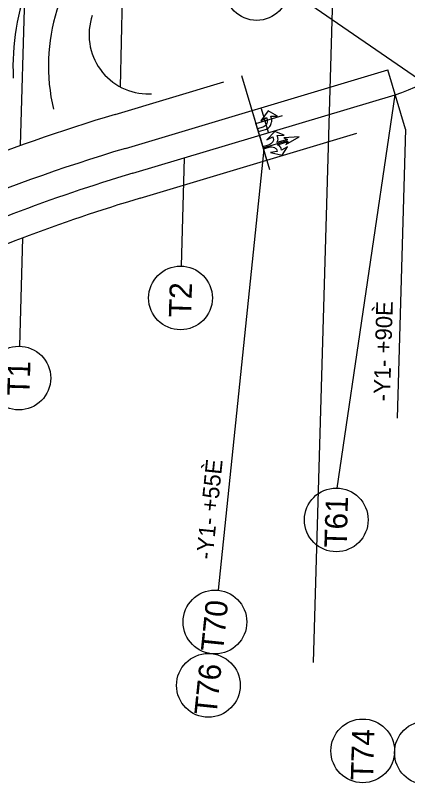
# Model space of a CAD drawing. Extents: x 1657109 to 2100937, y 684916 to 883211.
# Drawn here: x 2097527.1 to 2097693.3, y 685572.2 to 685898 of the extents above; entities that cross this region are included whole.
import ezdxf

# ---------------------------------------------------------------- set-up
doc = ezdxf.new("R2010")
doc.units = 0
for name, color, linetype in [('Default', 7, 'Continuous'), ('Prop CMT Pvmt Course 1', 7, 'Continuous'), ('Prop CMT Pvmt Gravel', 7, 'Continuous'), ('Prop Conc 1ft 6in Curb and Gutter', 7, 'Continuous'), ('Prop Conc 2ft 6in Curb and Gutter', 7, 'Continuous'), ('Prop Dimension', 7, 'Continuous'), ('Prop Guardrail Anchor Unit CELL', 7, 'Continuous'), ('Prop Lane Arrow CELL', 7, 'Continuous'), ('Prop Lane Lines', 7, 'Continuous'), ('Prop Paved Shoulder', 7, 'Continuous'), ('Prop Sign E Chevron Right', 7, 'Continuous'), ('Scratch_Level_1', 7, 'Continuous')]:
    doc.layers.add(name, color=color, linetype=linetype)

# ---------------------------------------------------------------- blocks, each defined once
blk = doc.blocks.new('SLRARR')
at = {"layer": 'Default'}
for points in [[(4.895, -0.375), (8.667, -0.375), (7.667, -1.187), (12.75, 0), (7.667, 1.187), (8.667, 0.375), (4.895, 0.375), (5.26, 0.719), (5.468, 0.983), (5.628, 1.319), (5.708, 1.595), (5.772, 1.944), (5.75, 2.563), (8, 2.063), (5.417, 4.187), (1.917, 2.188), (4.167, 2.563), (4.155, 2.076), (4.138, 1.788), (4.042, 1.499), (3.866, 1.247), (3.674, 0.995), (3.322, 0.743), (2.889, 0.551), (2.425, 0.431), (1.896, 0.37), (0, 0.375), (0, -0.375), (1.94, -0.375)], [(4.895, -0.375), (8.667, -0.375), (7.667, -1.187), (12.75, 0), (7.667, 1.187), (8.667, 0.375), (4.895, 0.375), (5.26, 0.719), (5.468, 0.983), (5.628, 1.319), (5.708, 1.595), (5.772, 1.944), (5.75, 2.563), (8, 2.063), (5.417, 4.187), (1.917, 2.188), (4.167, 2.563), (4.155, 2.076), (4.138, 1.788), (4.042, 1.499), (3.866, 1.247), (3.674, 0.995), (3.322, 0.743), (2.889, 0.551), (2.425, 0.431), (1.896, 0.37), (0, 0.375), (0, -0.375), (1.94, -0.375)], [(1.94, -0.375), (2.425, -0.43), (2.889, -0.55), (3.322, -0.742), (3.674, -0.994), (3.866, -1.247), (4.042, -1.499), (4.138, -1.788), (4.155, -2.076), (4.167, -2.563), (1.917, -2.188), (5.417, -4.187), (8, -2.062), (5.75, -2.563), (5.772, -1.944), (5.708, -1.595), (5.628, -1.319), (5.468, -0.982), (5.26, -0.718), (4.895, -0.375)], [(1.94, -0.375), (2.425, -0.43), (2.889, -0.55), (3.322, -0.742), (3.674, -0.994), (3.866, -1.247), (4.042, -1.499), (4.138, -1.788), (4.155, -2.076), (4.167, -2.563), (1.917, -2.188), (5.417, -4.187), (8, -2.062), (5.75, -2.563), (5.772, -1.944), (5.708, -1.595), (5.628, -1.319), (5.468, -0.982), (5.26, -0.718), (4.895, -0.375)]]:
    blk.add_lwpolyline(points, dxfattribs=at)

msp = doc.modelspace()

# ---------------------------------------------------------------- linework, layer by layer
at = {"layer": 'Prop CMT Pvmt Gravel'}
for p, q in [((2097571.62, 685867.71), (2097574.3, 685983.02)), ((2097529.26, 685842.85), (2097532.63, 685958.71)), ((2097642.82, 685909.02), (2097700.19, 685869.55)), ((2097663.44, 685697.81), (2097688.01, 685864.41)), ((2097692.39, 685849.78), (2097688.83, 685727.48)), ((2097632.3, 685841.3), (2097613.03, 685654.52)), ((2097597.45, 685791.82), (2097598.78, 685837.71)), ((2097528.95, 685757.9), (2097530.28, 685803.79))]:
    msp.add_line(p, q, dxfattribs=at)
for centre in [(2097629.33, 685909.41), (2097597.05, 685778.33), (2097528.55, 685744.4), (2097663.05, 685684.32), (2097611.64, 685641.09), (2097608.87, 685614.24), (2097674.26, 685586.49), (2097701.25, 685585.71)]:
    msp.add_circle(centre, 13.5, dxfattribs=at)
at = {"layer": 'Prop Conc 1ft 6in Curb and Gutter'}
msp.add_line((2097576.85, 685831.15), (2097688.01, 685864.41), dxfattribs=at)
msp.add_arc((2097791.55, 685113.58), 749, 106.65716, 114.87261, dxfattribs=at)
at = {"layer": 'Prop Conc 2ft 6in Curb and Gutter'}
msp.add_arc((2097665.53, 685934.68), 73.78, 287.7359, 0.5072, dxfattribs=at)
at = {"layer": 'Prop Dimension'}
for p, q in [((2097634.9, 685832.59), (2097623, 685872.38)), ((2097634.36, 685848.36), (2097631.35, 685858.42)), ((2097630.53, 685847.21), (2097627.52, 685857.27)), ((2097633.68, 685836.67), (2097630.53, 685847.21))]:
    msp.add_line(p, q, dxfattribs=at)
for points in [[(2097630.53, 685847.21), (2097629.02, 685852.24), (2097640.26, 685855.6)], [(2097630.53, 685847.21), (2097632.1, 685841.94), (2097642.44, 685845.04)]]:
    msp.add_lwpolyline(points, dxfattribs=at)
at = {"layer": 'Prop Guardrail Anchor Unit CELL'}
msp.add_line((2097580, 685820.61), (2097671.8, 685848.08), dxfattribs=at)
for centre, radius, start, end in [((2097621.08, 685876.69), 95, 132.4342, 183.1561), ((2097583.3, 685889.81), 25, 160.85, 271.3998), ((2097580.98, 685984.78), 120, 271.3998, 271.8221), ((2097791.55, 685113.58), 738, 106.65716, 114.87261)]:
    msp.add_arc(centre, radius, start, end, dxfattribs=at)
at = {"layer": 'Prop Lane Arrow CELL'}
msp.add_line((2097569.4, 685856.06), (2097615.37, 685869.82), dxfattribs=at)
msp.add_arc((2097791.55, 685113.58), 775, 106.65716, 111.99663, dxfattribs=at)
at = {"layer": 'Prop Lane Lines'}
msp.add_line((2097692.39, 685849.78), (2097684.86, 685874.95), dxfattribs=at)
at = {"layer": 'Prop Paved Shoulder'}
for points in [[(2097629.71, 685849.95), (2097630.05, 685848.8), (2097633.02, 685849.68), (2097633.56, 685849.88), (2097633.96, 685850.08), (2097634.37, 685850.36), (2097634.69, 685850.67), (2097634.92, 685850.95), (2097635.2, 685851.39), (2097635.37, 685851.76), (2097635.54, 685852.19), (2097635.67, 685852.72), (2097635.71, 685853.12), (2097635.71, 685853.66), (2097635.6, 685854.35), (2097635.32, 685855.28), (2097638.13, 685855.28), (2097634.19, 685857.65), (2097631.08, 685853.38), (2097633.5, 685854.73), (2097633.73, 685853.97), (2097633.83, 685853.53), (2097633.84, 685853.1), (2097633.79, 685852.75), (2097633.67, 685852.28), (2097633.54, 685851.94), (2097633.25, 685851.52), (2097632.88, 685851.17), (2097632.49, 685850.88), (2097631.91, 685850.61)], [(2097629.71, 685849.95), (2097630.05, 685848.8), (2097633.02, 685849.69), (2097633.56, 685849.88), (2097633.96, 685850.08), (2097634.37, 685850.36), (2097634.69, 685850.67), (2097634.92, 685850.96), (2097635.2, 685851.4), (2097635.37, 685851.76), (2097635.53, 685852.19), (2097635.67, 685852.72), (2097635.71, 685853.12), (2097635.71, 685853.66), (2097635.6, 685854.35), (2097635.32, 685855.28), (2097638.13, 685855.29), (2097634.19, 685857.65), (2097631.08, 685853.38), (2097633.5, 685854.73), (2097633.73, 685853.97), (2097633.83, 685853.53), (2097633.84, 685853.1), (2097633.79, 685852.75), (2097633.67, 685852.28), (2097633.54, 685851.94), (2097633.25, 685851.52), (2097632.88, 685851.17), (2097632.49, 685850.88), (2097631.91, 685850.61)]]:
    msp.add_lwpolyline(points, close=True, dxfattribs=at)
at = {"layer": 'Prop Sign E Chevron Right'}
msp.add_line((2097653.39, 685623.98), (2097672.88, 686294.24), dxfattribs=at)
at = {"layer": 'Scratch_Level_1'}
msp.add_line((2097573.7, 685841.69), (2097684.86, 685874.95), dxfattribs=at)
for centre, radius, start, end in [((2097621.08, 685876.69), 80, 132.4342, 193.3081), ((2097791.55, 685113.58), 760, 106.65716, 132.07604)]:
    msp.add_arc(centre, radius, start, end, dxfattribs=at)

# ---------------------------------------------------------------- block references
at = {"layer": 'Prop CMT Pvmt Course 1', "xscale": 1.25, "yscale": 1.2499999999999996, "rotation": 16.65716288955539}
msp.add_blockref('SLRARR', (2097632.1, 685841.94), dxfattribs=at)

# ---------------------------------------------------------------- texts
at = {"layer": 'Prop CMT Pvmt Gravel'}
for s, height, rotation, p in [('T2', 9.45, 88.3348, (2097601.54, 685770.02)), ('-Y1- +90È', 7, 88.3348, (2097685.81, 685734.47)), ('T1', 9.45, 88.3348, (2097533.06, 685736.77)), ('-Y1- +55È', 7, 84.1093, (2097610.6, 685667.39)), ('T61', 9.45, 88.3348, (2097667.43, 685672.44)), ('T70', 9.45, 84.1093, (2097615.06, 685628.17)), ('T76', 9.45, 84.1093, (2097612.28, 685601.29)), ('T74', 9.45, 88.3348, (2097678.63, 685573.9))]:
    msp.add_text(s, height=height, rotation=rotation, dxfattribs=at).set_placement(p)

doc.saveas('drawing.dxf')
